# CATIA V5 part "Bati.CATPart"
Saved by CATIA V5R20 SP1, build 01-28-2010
Part number: Bati
Bounding box of the stored display mesh (mm): x -70 to 70, y -8 to 60, z 0 to 54.844
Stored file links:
  E:\EDELI\gcausse\Edeli_2012_685_gcausse\Bati.CATPart
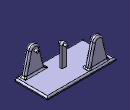
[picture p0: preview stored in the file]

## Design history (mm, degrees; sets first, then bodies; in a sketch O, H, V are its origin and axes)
Set1 "axe"
  Point1: type Center, Curve DatumCurve1
  DatumCurve1
  Line1: type PtDir, RefPoint Point1, Direction DatumCurve2, Start 0, End 20
  DatumCurve2
  Sketch1 on face of Pad2 from Sketch3.L1, origin (0, 5, 0), H (-1, 0, 0), V (0, 0, 1)
    line L1 (-22.698, 65) -> (70, 65)
    line L2 (70, 65) -> (70, 5)
    line L3 (70, 5) -> (-22.698, 5)
    line L4 (-22.698, 5) -> (-22.698, 65)
    reference intersected line E1 (-70, 5) -> (70, 5) from end face of Pad1
    reference projected point E2 (-22.698, 27.6563) from vertex [face of Pocket1 | face of Pocket1 | face of Pad2 from Sketch3.L1]
    horizontal: L1 H, L3 H
    vertical: L2 V, L4 V
    coincidence: L3 E1, L4 E2
Body1 (main body)
  Sketch2 on xy-plane, origin (0, 0, 0), H (1, 0, 0), V (0, 1, 0)
    line L1 (-70, 60) -> (70, 60)
    line L2 (70, 60) -> (70, -20)
    line L3 (70, -20) -> (-70, -20)
    line L4 (-70, -20) -> (-70, 60)
    distance L1 L3 = 80
    distance L3 H = 20
    horizontal: L1 H, L3 H
    vertical: L2 V, L4 V
  Pad1: profile Sketch2, direction (0, 0, 1), length 5
  Sketch3 on end face of Pad1, origin (0, 0, 5), H (1, 0, 0), V (0, 1, 0)
    line L1 (-60, 5) -> (60, 5)
    line L2 (60, 5) -> (60, -5)
    line L3 (60, -5) -> (-60, -5)
    line L4 (-60, -5) -> (-60, 5)
    reference projected line E1 (70, 60) -> (-70, 60) from edge [face of Pad1 from Sketch2.L1 | end face of Pad1]
    distance L1 E1 = 55
    distance L3 L1 = 10
    horizontal: L1 H, L3 H
    vertical: L2 V, L4 V
  Pad2: profile Sketch3, direction (0, 0, 1), length 60
  Sketch4 on face of Pad2 from Sketch3.L1, origin (0, 5, 0), H (-1, 0, 0), V (0, 0, 1)
    point P1 (-60, 5)
    line L1 (-60, 5) -> (-49.7178, 47.3589)
    arc A1 centre (-40, 45) radius 10 from (-49.7178, 47.3589) to (-30.3407, 47.5882) cw
    point P3 (-40, 45)
    line L2 (-30.3407, 47.5882) -> (-25, 27.6563)
    point P5 (-25, 27.6563)
    point P6 (25, 27.6563)
    point P7 (40, 45)
    line L3 (60, 5) -> (60, 99.8515)
    line L4 (60, 99.8515) -> (-60, 99.8515)
    line L5 (-60, 99.8515) -> (-60, 5)
    reference projected line E1 (60, 5) -> (60, 65) from edge [face of Pad2 from Sketch3.L4 | face of Pad2 from Sketch3.L1]
    reference projected line E2 (-60, 65) -> (60, 65) from edge [face of Pad2 from Sketch3.L1 | end face of Pad2]
    reference projected line E3 (-60, 65) -> (60, 65) from edge [face of Pad2 from Sketch3.L1 | end face of Pad2]
    reference projected line E4 (-60, 5) -> (-60, 65) from edge [face of Pad2 from Sketch3.L1 | face of Pad2 from Sketch3.L2]
    line L6 (-25, 27.6563) -> (-18.9293, 5)
    line L7 (-18.9293, 5) -> (60, 5)
    reference projected line E5 (-60, 5) -> (60, 5) from edge [end face of Pad1 | face of Pad2 from Sketch3.L1]
    reference projected line E6 (-60, 5) -> (60, 5) from edge [end face of Pad1 | face of Pad2 from Sketch3.L1]
    distance P5 L5 = 35
    distance P3 E2 = 20
    distance P7 E3 = 20
    radius A1 = 10
    distance P3 P7 = 80
    distance E5 P1 = 0
    distance L7 E6 = 0
    tangency: A1 L1, L2 A1, L6 A1
    vertical: L3 V, L5 V
    horizontal: L4 H, L7 H
    coincidence: E1 L3, L5 E4
  Pocket1: profile Sketch4, direction (0, -1, 0), length 10
  Sketch5 on element of Sketch1, origin (0, 0, 5), H (1, 0, 0), V (0, 1, 0)
    line L1 (-60, 55) -> (-20, 55)
    line L2 (-20, 55) -> (-20, 45)
    line L3 (-20, 45) -> (-60, 45)
    line L4 (-60, 45) -> (-60, 55)
    reference projected line E1 (70, 60) -> (-70, 60) from edge [face of Pad1 from Sketch2.L1 | end face of Pad1]
    distance L3 E1 = 15
    horizontal: L1 H, L3 H
    vertical: L2 V, L4 V
  Pad3: profile Sketch5, direction (0, 0, 1), length 60
  Sketch6 on face of Pad3 from Sketch5.L3, origin (0, 45, 0), H (1, 0, 0), V (0, 0, 1)
    point P1 (-60, 5)
    line L1 (-60, 5) -> (-49.7178, 47.3589)
    arc A1 centre (-40, 45) radius 10 from (-49.7178, 47.3589) to (-30.2822, 47.3589) cw
    point P3 (-40, 45)
    line L2 (-30.2822, 47.3589) -> (-20, 5)
    point P5 (-20, 5)
    line L3 (-20, 5) -> (-20, 75)
    line L4 (-20, 75) -> (-60, 75)
    line L5 (-60, 75) -> (-60, 5)
    reference projected line E1 (-60, 5) -> (-20, 5) from edge [element of Sketch1 | face of Pad3 from Sketch5.L3]
    reference projected point E2 (-20, 5) from vertex [face of Pad3 from Sketch5.L2 | element of Sketch1 | face of Pad3 from Sketch5.L3]
    reference projected point E3 (-60, 5) from vertex [face of Pad3 from Sketch5.L3 | element of Sketch1 | face of Pad3 from Sketch5.L4]
    radius A1 = 10
    distance P3 E1 = 40
    tangency: A1 L1, L2 A1
    vertical: L3 V, L5 V
    horizontal: L4 H
    coincidence: P5 E2, P1 E3
    equidistance: L3 L5 P3
  Pocket2: profile Sketch6, direction (0, 1, 0), length 60
  Fillet1: radius 3, on face of Pocket2 from Sketch6.L1
  Fillet2: radius 3, on edge [face of Pocket1 | face of Pad2 from Sketch3.L3]
  Fillet3: radius 3, on face of Pocket1
  Fillet4: radius 3, on edge [face of Pad2 from Sketch3.L1 | face of Pocket1 from Sketch4.L1]
  Sketch7 on face of Pad3 from Sketch5.L3, origin (0, 45, 0), H (1, 0, 0), V (0, 0, 1)
    circle A1 centre (-40, 45) radius 2.5
    reference projected point E1 (-40, 45) from axis of face of Pocket2 from Sketch6.A1
    radius A1 = 2.5
    concentricity: A1 E1
  Pad4: profile Sketch7, direction (0, -1, 0), length 5
  Sketch8 on face of Pocket1, origin (0, 0, 5), H (1, 0, 0), V (0, 1, 0)
    line L1 (-5, 25) -> (5, 25)
    line L2 (5, 25) -> (5, 20)
    line L3 (5, 20) -> (-5, 20)
    line L4 (-5, 20) -> (-5, 25)
    reference projected line E1 (-70, -20) -> (70, -20) from edge [face of Pad1 from Sketch2.L3 | face of Fillet3]
    reference projected line E2 (70, -20) -> (70, 60) from edge [face of Pad1 from Sketch2.L2 | face of Fillet3]
    distance L1 L3 = 5
    distance L3 E1 = 40
    distance L4 L2 = 10
    distance L2 E2 = 65
    horizontal: L1 H, L3 H
    vertical: L2 V, L4 V
  Pad5: profile Sketch8, direction (0, 0, 1), length 50
  Sketch9 on face of Pad5 from Sketch8.L1, origin (0, 25, 0), H (-1, 0, 0), V (0, 0, 1)
    point P1 (-5, 5)
    line L1 (-5, 5) -> (-5, 45)
    arc A1 centre (0, 45) radius 5 from (-5, 45) to (5, 45) cw
    point P3 (0, 45)
    line L2 (5, 45) -> (5, 5)
    point P5 (5, 5)
    line L3 (5, 5) -> (5, 65)
    line L4 (5, 65) -> (-5, 65)
    point P7 (-5, 65)
    line L5 (-5, 65) -> (-5, 5)
    reference projected point E1 (-5, 5) from vertex [face of Pad5 from Sketch8.L2 | face of Pocket1 | face of Pad5 from Sketch8.L1]
    reference projected point E2 (5, 5) from vertex [face of Pad5 from Sketch8.L1 | face of Pocket1 | face of Pad5 from Sketch8.L4]
    reference projected line E3 (-5, 5) -> (5, 5) from edge [face of Pocket1 | face of Pad5 from Sketch8.L1]
    distance P3 E3 = 40
    vertical: L1 V, L5 V
    tangency: A1 L1, L2 A1, L3 A1
    coincidence: P7 L1, P1 E1, P5 E2
    horizontal: L4 H
  Pocket3: profile Sketch9, direction (0, -1, 0), length 50
  Sketch10 on face of Pad5 from Sketch8.L1, origin (0, 25, 0), H (-1, 0, 0), V (0, 0, 1)
    circle A1 centre (0, 45) radius 2.5
    reference projected arc E1 centre (0, 45) radius 5 from (5, 45) to (-5, 45) ccw from edge [face of Pad5 from Sketch8.L1 | face of Pocket3 from Sketch9.A1]
    reference projected arc E2 centre (0, 45) radius 5 from (5, 45) to (-5, 45) ccw from edge [face of Pad5 from Sketch8.L1 | face of Pocket3 from Sketch9.A1]
    radius A1 = 2.5
    radius E2 = 5 (reference)
    concentricity: A1 E1
  Pad6: profile Sketch10, direction (0, 1, 0), length 5, opposite side length 10
  DatumCurve3
  Sketch11 on face of Pad2 from Sketch3.L1, origin (0, 5, 0), H (-1, 0, 0), V (0, 0, 1)
    circle A1 centre (-40, 45) radius 2.5
    reference projected arc E1 centre (-40, 45) radius 7 from (-33.5888, 42.1899) to (-42.9404, 38.6475) ccw from edge of DatumCurve3
    reference projected arc E2 centre (-40, 45) radius 7 from (-33.5888, 42.1899) to (-42.9404, 38.6475) ccw from edge of DatumCurve3
    radius A1 = 2.5
    radius E2 = 7 (reference)
    concentricity: A1 E1
  Pad7: profile Sketch11, direction (0, 1, 0), length 5
  Sketch12 on face of Pocket1, origin (0, 0, 5), H (1, 0, 0), V (0, 1, 0)
    line L1 (-100, -8) -> (100, -8)
    line L2 (100, -8) -> (100, -28)
    line L3 (100, -28) -> (-100, -28)
    line L4 (-100, -28) -> (-100, -8)
    reference projected line E1 (56.1847, -8) -> (22.8389, -8) from edge [face of Fillet3 | face of Pocket1]
    horizontal: L1 H, L3 H
    vertical: L2 V, L4 V
    coincidence: L1 E1
  Pocket4: profile Sketch12, direction (0, 0, -1), length 5
  Fillet5: radius 3, on edge [face of Pocket1 | face of Pocket4 from Sketch12.L1] (x2); edge [face of Fillet3 | face of Pocket4 from Sketch12.L1]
